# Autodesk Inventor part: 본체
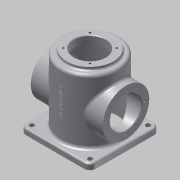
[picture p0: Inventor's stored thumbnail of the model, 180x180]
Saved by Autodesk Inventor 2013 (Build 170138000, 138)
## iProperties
Created: 2015-10
Part Number: 본체
Material: 알루미늄 6061
Document SubType Name: Modeling
Designer: user-11
Density: 1 g/cm^3
Author: user-11
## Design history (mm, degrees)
sketch "스케치1"
  geometry: L1 (-60, -60)-(60, -60); L2 (60, -60)-(60, 60); L3 (60, 60)-(-60, 60); L4 (-60, 60)-(-60, -60); 1 further point
  constraints: 8 end point, 2 parallel, 1 horizontal, 1 perpendicular
  dimensions: "d0" = 120 distance of L1.start L1.end; "d2" = 120 distance of L1.end L2.end; "d3" = 60 distance from line of point (0, 0) L1; "d4" = 60 distance from line of L2 point (0, 0)
extrude "돌출1" new body sketch "스케치1" distance "d5" = 10; taper "d6" = 0 deg
sketch "스케치2"
  geometry: C1 r 50 at (0, 0); 1 further point
  constraints: 1 centre point, 1 coincident
  dimensions: "d7" = 100 diameter of C1
extrude "돌출2" join sketch "스케치2" distance "d9" = 110; taper "d10" = 0 deg
node "작업 평면1"
sketch "스케치4"
  geometry: C1 r 50 at (0, 0) reference; C2 r 40 at (0, 0)
  constraints: 1 centre point, 1 coincident
  dimensions: "d17" = 80 diameter of C2
extrude "돌출4" join sketch "스케치4" distance "d19" = 5; taper "d20" = 0 deg
sketch "스케치5"
  geometry: C1 r 40 at (0, 0) reference; C2 r 27 at (0, 0)
  constraints: 1 centre point, 1 coincident
  dimensions: "d21" = 54 diameter of C2
extrude "돌출5" cut sketch "스케치5" distance "d23" = 13; taper "d24" = 0 deg
sketch "스케치6"
  geometry: C1 r 27 at (0, 0) reference; C2 r 45 at (0, 0)
  constraints: 1 centre point, 1 coincident
  dimensions: "d25" = 90 diameter of C2
extrude "돌출6" cut sketch "스케치6" distance "d27" = 112; taper "d28" = 0 deg
sketch "스케치10" dims "d57" = 65
  geometry: L1 (32.5, 0)-(-32.5, 0); L2 (0, 32.5)-(0, -32.5); L3 (0, 0)-(-22.981, 22.981); L4 (0, 0)-(-22.981, -22.981); L5 (0, 0)-(22.981, -22.981); L6 (0, 0)-(22.981, 22.981); C1 r 27 at (0, 0) reference
  constraints: 12 end point, 4 perpendicular, 1 horizontal, 10 other
  dimensions: "d59" = 0 distance of C1.centre L3.start; "d60" = 0 distance from line of C1.centre L2; "d61" = 0 distance from line of C1.centre L1; "d62" = 45 deg angle of L6 L1
hole "구멍3" sketch "스케치10" at (-22.981, 22.981), (22.981, 22.981), (22.981, -22.981), (-22.981, -22.981) diameter "d63" = 3.242; stored, may be unused: countersink angle "d67" = 90 deg, drill point angle "d69" = 118 deg; dims "d64" = 8, "d65" = 4, "d66" = 2, "d68" = 10
fillet "모깎기1" dims "d70" = 10
sketch "스케치11"
  geometry: C1 r 4 at (-50, -50); C2 r 4 at (50, -50); C3 r 4 at (50, 50); C4 r 4 at (-50, 50); A1 r 10 centre (-50, 50) between (-50, 60) and (-60, 50) reference; A2 r 10 centre (-50, -50) between (-60, -50) and (-50, -60) reference; A3 r 10 centre (50, -50) between (50, -60) and (60, -50) reference; A4 r 10 centre (50, 50) between (60, 50) and (50, 60) reference
  constraints: 4 centre point, 3 coincident
  dimensions: "d71" = 8 diameter of C1; "d73" = 0 distance of A3.centre C2.centre; "d74" = 0 distance of A3.centre C2.centre; "d75" = 8 diameter of C4; "d76" = 8 diameter of C3; "d77" = 8 diameter of C2
extrude "돌출8" cut sketch "스케치11" stored distance "d78" = 112; taper "d79" = 0 deg
fillet "모깎기2" dims "d80" = 3
fillet "모깎기5" dims "d83" = 5
fillet "모깎기6" dims "d84" = 5
fillet "모깎기7" dims "d85" = 3
chamfer "모따기1" distance "d86" = 3; stored, may be unused: second distance "d87" = 2, angle "d88" = 45 deg
node "작업 평면2"
sketch "스케치12"
  geometry: L1 (-6.946, 39.515)-(-6.946, 100.485); L2 (-6.946, 100.485)-(6.946, 100.485); L3 (6.946, 100.485)-(6.946, 39.515); L4 (6.946, 39.515)-(-6.946, 39.515); L5 (0, 39.515)-(0, 100.485); L6 (-6.946, 70)-(6.946, 70); L7 (0, 0)-(0, 149.644)
  constraints: 6 end point, 4 midpoint, 1 vertical, 2 other
  dimensions: "d99" = 70 distance from line of L7.start L6; "d100" = 0 distance from line of L7.start L5; "d103" = 0 distance between parallel lines of L7 L5
feature "엠보싱1" sketch "스케치12" dims "d0" = 120, "d2" = 120, "d3" = 60, "d4" = 60, "d104" = 0.5, "d105" = 0
chamfer "모따기3" distance "d106" = 1; stored, may be unused: second distance "d107" = 2, angle "d108" = 45 deg
node "작업 평면6"
sketch "스케치13"
  geometry: C1 r 40 at (0, 60); 1 further point
  constraints: 1 centre point
  dimensions: "d110" = 80 diameter of C1; "d112" = 60 distance of point (0, 0) C1.centre; "d114" = 0 horizontal distance of point (0, 0) C1.centre
extrude "돌출9" join sketch "스케치13" distance "d115" = 40; taper "d116" = 0 deg
sketch "스케치14"
  geometry: C1 r 45 at (0, 0) reference
extrude "돌출10" cut sketch "스케치14" distance "d117" = 112; taper "d118" = 0 deg
sketch "스케치15"
  geometry: C1 r 40 at (0, 0) reference; C2 r 27 at (0, 0); 1 further point
  constraints: 1 centre point, 1 coincident
  dimensions: "d119" = 54 diameter of C2
extrude "돌출11" cut sketch "스케치15" stored distance "d121" = 112; taper "d122" = 0 deg
sketch "스케치16" dims "d123" = 65
  geometry: L1 (0, 0)-(-32.5, 0); C1 r 40 at (0, 0) reference; 1 further point
  constraints: 2 end point, 1 coincident, 1 horizontal, 1 horizontal alignment, 2 other
hole "구멍4" sketch "스케치16" at (-32.5, 0) diameter "d125" = 3.242; stored, may be unused: countersink angle "d129" = 90 deg, drill point angle "d131" = 118 deg; dims "d126" = 8, "d127" = 4, "d128" = 2, "d130" = 10
fillet "모깎기8" dims "d135" = 5
sketch "스케치17"
  geometry: C1 r 45 at (0, 0) reference
extrude "돌출12" cut sketch "스케치17" distance "d136" = 112; taper "d137" = 0 deg
fillet "모깎기9" dims "d138" = 3
chamfer "모따기4" distance "d139" = 1; stored, may be unused: second distance "d140" = 2, angle "d141" = 45 deg
node "솔리드1"
mirror "대칭2"
pattern_circular "원형 패턴3" dims angle "d133" = 360 deg
mirror "대칭3"
other parameters: "d11" = 62.5, "d92" = -60.75, "d109" = 62
